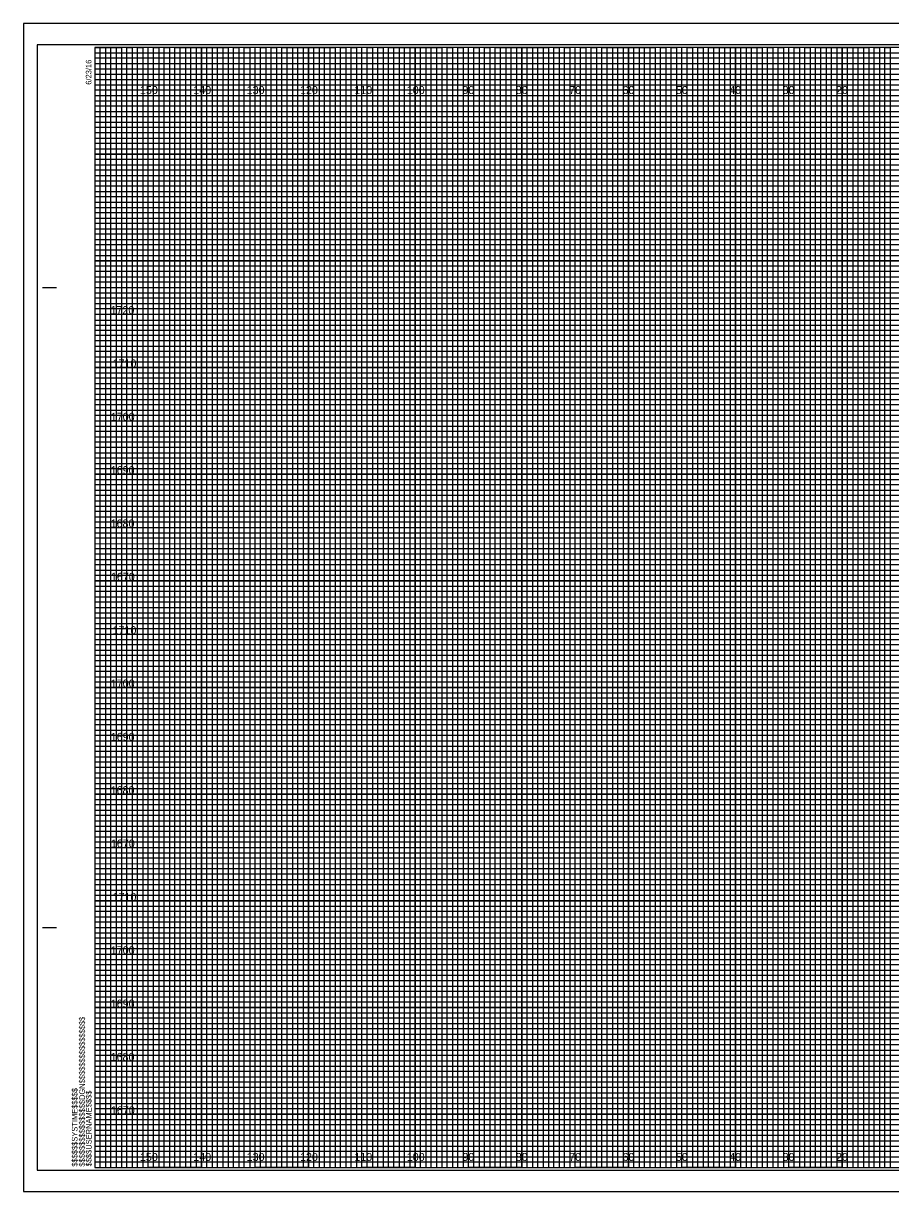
# Model space of a CAD drawing. Extents: x -13 to 323, y -5 to 434.
# Drawn here: x -13.4 to 149.1, y 215.5 to 434.5 of the extents above; entities that cross this region are included whole.
import ezdxf

# ---------------------------------------------------------------- set-up
doc = ezdxf.new("R2010")
doc.units = 0
for name, color, linetype in [('Prop Horizontal Alignment', 7, 'Continuous'), ('Raster_Level_0', 7, 'Continuous'), ('Sheet Cross Section CELL', 7, 'Continuous'), ('Sheet Cross Section Grid Major CELL', 7, 'Continuous'), ('Sheet Cross Section Grid Middle CELL', 7, 'Continuous'), ('Sheet Cross Section Grid Minor 1 CELL', 7, 'Continuous'), ('Sheet Cross Section Grid Minor 2 CELL', 7, 'Continuous'), ('Sheet Cutting Line CELL', 7, 'Continuous'), ('Sheet DOT Grid CELL', 7, 'Continuous'), ('Sheet Plot Border Inside CELL', 7, 'Continuous'), ('Sheet Plot Border Outside CELL', 7, 'Continuous')]:
    doc.layers.add(name, color=color, linetype=linetype)

msp = doc.modelspace()

# ---------------------------------------------------------------- linework, layer by layer
at = {"layer": 'Sheet Cross Section CELL'}
for p, q in [((-9.8, 385), (-7.3, 385)), ((-9.7, 385), (-7.2, 385)), ((-9.8, 265), (-7.3, 265)), ((-9.7, 265), (-7.2, 265)), ((0, 220), (0, 220)), ((0, 220), (0, 220)), ((0, 220), (0, 220)), ((0, 220), (0, 220)), ((0, 220), (0, 220)), ((0, 220), (0, 220)), ((0, 220), (0, 220))]:
    msp.add_line(p, q, dxfattribs=at)
msp.add_lwpolyline([(320, 430), (0, 430), (0, 220), (320, 220)], close=True, dxfattribs=at)
at = {"layer": 'Sheet Cross Section Grid Major CELL'}
for p, q in [((10, 430), (0, 430)), ((10, 220), (10, 430)), ((30, 430), (20, 430)), ((20, 430), (20, 220)), ((30, 220), (30, 430)), ((50, 430), (40, 430)), ((40, 430), (40, 220)), ((50, 220), (50, 430)), ((70, 430), (60, 430)), ((60, 430), (60, 220)), ((70, 220), (70, 430)), ((90, 430), (80, 430)), ((80, 430), (80, 220)), ((90, 220), (90, 430)), ((110, 430), (100, 430)), ((100, 430), (100, 220)), ((110, 220), (110, 430)), ((130, 430), (120, 430)), ((120, 430), (120, 220)), ((130, 220), (130, 430)), ((150, 430), (140, 430)), ((140, 430), (140, 220)), ((20, 220), (10, 220)), ((40, 220), (30, 220)), ((60, 220), (50, 220)), ((80, 220), (70, 220)), ((100, 220), (90, 220)), ((120, 220), (110, 220)), ((140, 220), (130, 220))]:
    msp.add_line(p, q, dxfattribs=at)
for points in [[(0, 420), (320, 420), (320, 410), (0, 410)], [(0, 400), (320, 400), (320, 390), (0, 390)], [(0, 380), (320, 380), (320, 370), (0, 370)], [(0, 360), (320, 360), (320, 350), (0, 350)], [(0, 340), (320, 340), (320, 330), (0, 330)], [(0, 320), (320, 320), (320, 310), (0, 310)], [(0, 300), (320, 300), (320, 290), (0, 290)], [(0, 280), (320, 280), (320, 270), (0, 270)], [(0, 260), (320, 260), (320, 250), (0, 250)], [(0, 240), (320, 240), (320, 230), (0, 230)]]:
    msp.add_lwpolyline(points, dxfattribs=at)
at = {"layer": 'Sheet Cross Section Grid Middle CELL'}
for points in [[(0, 430), (5, 430), (5, 220), (15, 220), (15, 430), (25, 430), (25, 220), (35, 220), (35, 430), (45, 430), (45, 220), (55, 220), (55, 430), (65, 430), (65, 220), (75, 220), (75, 430), (85, 430), (85, 220), (95, 220), (95, 430), (105, 430), (105, 220), (115, 220), (115, 430), (125, 430), (125, 220), (135, 220), (135, 430), (145, 430), (145, 220), (155, 220)], [(0, 425), (275, 425)], [(0, 405), (320, 405), (320, 415), (0, 415)], [(0, 385), (320, 385), (320, 395), (0, 395)], [(0, 365), (320, 365), (320, 375), (0, 375)], [(0, 345), (320, 345), (320, 355), (0, 355)], [(0, 325), (320, 325), (320, 335), (0, 335)], [(0, 305), (320, 305), (320, 315), (0, 315)], [(0, 285), (320, 285), (320, 295), (0, 295)], [(0, 265), (320, 265), (320, 275), (0, 275)], [(0, 245), (320, 245), (320, 255), (0, 255)], [(0, 225), (320, 225), (320, 235), (0, 235)]]:
    msp.add_lwpolyline(points, dxfattribs=at)
at = {"layer": 'Sheet Cross Section Grid Minor 1 CELL'}
for p, q in [((0, 429), (260, 429)), ((260, 427.98), (0, 427.98)), ((0, 427.98), (0, 427)), ((0, 427), (260, 427)), ((260, 425.89), (0, 425.89)), ((0, 425.89), (0, 424)), ((0, 424), (320, 424))]:
    msp.add_line(p, q, dxfattribs=at)
for points in [[(0, 423), (270, 423), (320, 423), (320, 422), (0, 422)], [(0, 421), (320, 421), (320, 419), (0, 419)], [(0, 418), (320, 418), (320, 417), (0, 416.98)], [(0, 416), (320, 416), (320, 414), (0, 414)], [(0, 413), (320, 413), (320, 412), (0, 412)], [(0, 411), (320, 411), (320, 409), (0, 409)], [(0, 408), (320, 408), (320, 407), (0, 407)], [(0, 406), (320, 406), (320, 404), (0, 404)], [(0, 403), (320, 403), (320, 402), (0, 402)], [(0, 401), (320, 401), (320, 399), (0, 399)], [(0, 398), (320, 398), (320, 397), (0, 397)], [(0, 396), (320, 396), (320, 393.95), (320, 393), (320, 392), (0, 392)], [(0, 394), (320, 394), (320, 393), (0, 393)], [(0, 391), (320, 391), (320, 389), (0, 389.03)], [(0, 389.03), (320, 389), (320, 388), (0, 388)], [(0, 387), (320, 387), (320, 386), (0, 386)], [(0, 384), (320, 384), (320, 383), (0, 383)], [(0, 382), (320, 382), (320, 381), (0, 381)], [(-0.07, 378.89), (320, 378.89), (320, 377.88), (-0.07, 377.88)], [(0, 377), (320, 377), (320, 376), (0, 376)], [(0, 374), (320, 374), (320, 373), (0, 373)], [(0, 372), (320, 372), (320, 371), (0, 371)], [(0, 369), (320, 369), (320, 368), (0, 368)], [(0, 367), (320, 367), (320, 366), (0, 366)], [(0, 364), (320, 364), (320, 363), (0, 363)], [(0, 362), (320, 362), (320, 361), (0, 361)], [(0, 359), (320, 359), (319.99, 357.98), (0, 358)], [(0, 357), (320, 357), (320, 356), (0, 356)], [(0, 354), (320, 354), (320, 353), (0, 353)], [(0, 352), (320, 352), (320, 351), (0, 351)], [(0, 349), (320, 349), (320, 348), (0, 348)], [(0, 347), (320, 347), (320, 346), (0, 346)], [(0, 344), (320, 344), (320, 343), (0, 343)], [(0, 342), (320, 342), (320, 341), (0, 341)], [(0, 339), (320, 339), (320, 338), (0, 338)], [(0, 336.99), (320.07, 336.91), (320, 336), (0, 336)], [(0, 334), (320, 334), (320, 333), (0, 333)], [(0, 332), (320, 332), (320, 331), (0, 331)], [(0, 329), (320, 329), (320, 328), (0, 328)], [(0, 327), (320, 327), (320, 326), (0, 326)], [(0, 324), (320, 324), (320, 323), (0, 323)], [(0, 322), (320, 322), (320, 321), (0, 321)], [(0, 319), (320, 319), (320, 318), (0, 318)], [(0, 317), (320, 317), (320, 316), (0, 316)], [(0, 314), (320, 314), (320, 313), (0, 313)], [(0, 312), (320, 312), (320, 311), (0, 311)], [(0, 309), (320, 309), (320, 308), (0, 308)], [(0, 307), (320, 307), (320, 306), (0, 306)], [(0, 304), (320, 304), (320, 303), (0, 303)], [(0, 302), (320, 302), (320, 301), (0, 301)], [(0, 299), (320, 299), (319.99, 297.98), (0, 298)], [(0, 297), (320, 297), (320, 296), (0, 296)], [(0, 294), (320, 294), (320, 293), (0, 293)], [(0, 292), (320, 292), (320, 291), (0, 291)], [(0, 289), (320, 289), (320, 288), (0, 288)], [(0, 287), (320, 287), (320, 286), (0, 286)], [(0, 284), (320, 284), (320, 283), (0, 283)], [(0, 282), (320, 282), (320, 281), (0, 281)], [(0, 279), (320, 279), (320, 278), (0, 278)], [(0, 276.99), (320.07, 276.91), (320, 276), (0, 276)], [(0, 274), (320, 274), (320, 273), (0, 273)], [(0, 272), (320, 272), (320, 271), (0, 271)], [(0, 269), (320, 269), (320, 268), (0, 268)], [(0, 267), (320, 267), (320, 266), (0, 266)], [(0, 264), (320, 264), (320, 263), (0, 263)], [(0, 262), (320, 262), (320, 261), (0, 261)], [(0, 259), (320, 259), (320, 258), (0, 258)], [(0, 257), (320, 257), (320, 256), (0, 256)], [(0, 254), (320, 254), (320, 253), (0, 253)], [(0, 252), (320, 252), (320, 251), (0, 251)], [(0, 249), (320, 249), (320, 248), (0, 248)], [(0, 247), (320, 247), (320, 246), (0, 246)], [(0, 244), (320, 244), (320, 243), (0, 243)], [(0, 242), (320, 242), (320, 241), (0, 241)], [(0, 239), (320, 239), (320, 238), (0, 238)], [(0, 237), (320, 237), (320, 236), (0, 236)], [(0, 234), (320, 234), (320, 233), (0, 233)], [(0, 232), (320, 232), (320, 231), (0, 231)], [(0, 229), (320, 229), (320, 228), (0, 228)], [(0, 227), (320, 227), (320, 226), (0, 226)], [(0, 224), (320, 224), (320, 223), (0, 223)], [(0, 222), (320, 222), (320, 221), (0, 221)]]:
    msp.add_lwpolyline(points, dxfattribs=at)
at = {"layer": 'Sheet Cross Section Grid Minor 2 CELL'}
for points in [[(0, 220), (1, 220), (1, 430), (2, 430), (2, 220)], [(2, 220), (3, 220), (3, 430), (4, 430), (4, 220)], [(5, 220), (6, 220), (6, 430), (7, 430), (7, 220)], [(7, 220), (8, 220), (8, 430), (9, 430), (9, 220)], [(10, 220), (11, 220), (11, 430), (12, 430), (12, 220)], [(12, 220), (13, 220), (13, 430), (14, 430), (14, 220)], [(15, 220), (16, 220), (16, 430), (17, 430), (17, 220)], [(17, 220), (18, 220), (18, 430), (19, 430), (19, 220)], [(20, 220), (21, 220), (21, 430), (22, 430), (22, 220)], [(22, 220), (23, 220), (23, 430), (24, 430), (24, 220)], [(25, 220), (26, 220), (26, 430), (27, 430), (27, 220)], [(27, 220), (28, 220), (28, 430), (29, 430), (29, 220)], [(30, 220), (31, 220), (31, 430), (32, 430), (32, 220)], [(32, 220), (33, 220), (33, 430), (34, 430), (34, 220)], [(35, 220), (36, 220), (36, 430), (37, 430), (37, 220)], [(37, 220), (38, 220), (38, 430), (39, 430), (39, 220)], [(40, 220), (41, 220), (41, 430), (42, 430), (42, 220)], [(42, 220), (43, 220), (43, 430), (44, 430), (44, 220)], [(45, 220), (46, 220), (46, 430), (47, 430), (47, 220)], [(47, 220), (48, 220), (48, 430), (49, 430), (49, 220)], [(50, 220), (51, 220), (51, 430), (52, 430), (52, 220)], [(52, 220), (53, 220), (53, 430), (54, 430), (54, 220)], [(55, 220), (56, 220), (56, 430), (57, 430), (57, 220)], [(57, 220), (58, 220), (58, 430), (59, 430), (59, 220)], [(60, 220), (61, 220), (61, 430), (62, 430), (62, 220)], [(62, 220), (63, 220), (63, 430), (64, 430), (64, 220)], [(65, 220), (66, 220), (66, 430), (67, 430), (67, 220)], [(67, 220), (68, 220), (68, 430), (69, 430), (69, 220)], [(70, 220), (71, 220), (71, 430), (72, 430), (72, 220)], [(72, 220), (73, 220), (73, 430), (74, 430), (74, 220)], [(75, 220), (76, 220), (76, 430), (77, 430), (77, 220)], [(77, 220), (78, 220), (78, 430), (79, 430), (79, 220)], [(80, 220), (81, 220), (81, 430), (82, 430), (82, 220)], [(82, 220), (83, 220), (83, 430), (84, 430), (84, 220)], [(85, 220), (86, 220), (86, 430), (87, 430), (87, 220)], [(87, 220), (88, 220), (88, 430), (89, 430), (89, 220)], [(90, 220), (91, 220), (91, 430), (92, 430), (92, 220)], [(92, 220), (93, 220), (93, 430), (94, 430), (94, 220)], [(95, 220), (96, 220), (96, 430), (97, 430), (97, 220)], [(97, 220), (98, 220), (98, 430), (99, 430), (99, 220)], [(100, 220), (101, 220), (101, 430), (102, 430), (102, 220)], [(102, 220), (103, 220), (103, 430), (104, 430), (104, 220)], [(105, 220), (106, 220), (106, 430), (107, 430), (107, 220)], [(107, 220), (108, 220), (108, 430), (109, 430), (109, 220)], [(110, 220), (111, 220), (111, 430), (112, 430), (112, 220)], [(112, 220), (113, 220), (113, 430), (114, 430), (114, 220)], [(115, 220), (116, 220), (116, 430), (117, 430), (117, 220)], [(117, 220), (118, 220), (118, 430), (119, 430), (119, 220)], [(120, 220), (121, 220), (121, 430), (122, 430), (122, 220)], [(122, 220), (123, 220), (123, 430), (124, 430), (124, 220)], [(125, 220), (126, 220), (126, 430), (127, 430), (127, 220)], [(127, 220), (128, 220), (128, 430), (129, 430), (129, 220)], [(130, 220), (131, 220), (131, 430), (132, 430), (132, 220)], [(132, 220), (133, 220), (133, 430), (134, 430), (134, 220)], [(135, 220), (136, 220), (136, 430), (137, 430), (137, 220)], [(137, 220), (138, 220), (138, 430), (139, 430), (139, 220)], [(140, 220), (141, 220), (141, 430), (142, 430), (142, 220)], [(142, 220), (143, 220), (143, 430), (144, 430), (144, 220)], [(145, 220), (146, 220), (146, 430), (147, 430), (147, 220)], [(147, 220), (148, 220), (148, 430), (149, 430), (149, 220)]]:
    msp.add_lwpolyline(points, dxfattribs=at)
at = {"layer": 'Sheet Cutting Line CELL'}
for p, q in [((323.3, 434.5), (-13.4, 434.5)), ((-13.4, 434.5), (-13.4, 215.5)), ((-13.4, 215.5), (323.3, 215.5))]:
    msp.add_line(p, q, dxfattribs=at)
at = {"layer": 'Sheet DOT Grid CELL'}
for p, q in [((10, 220), (10, 430)), ((20, 220), (20, 430)), ((30, 220), (30, 430)), ((40, 220), (40, 430)), ((50, 220), (50, 430)), ((60, 220), (60, 430)), ((70, 220), (70, 430)), ((80, 220), (80, 430)), ((90, 220), (90, 430)), ((100, 220), (100, 430)), ((110, 220), (110, 430)), ((120, 220), (120, 430)), ((130, 220), (130, 430)), ((140, 220), (140, 430)), ((0, 420), (320, 420)), ((0, 410), (320, 410)), ((0, 400), (320, 400)), ((0, 390), (320, 390)), ((0, 380), (320, 380)), ((0, 370), (320, 370)), ((0, 360), (320, 360)), ((0, 350), (320, 350)), ((0, 340), (320, 340)), ((0, 330), (320, 330)), ((0, 320), (320, 320)), ((0, 310), (320, 310)), ((0, 300), (320, 300)), ((0, 290), (320, 290)), ((0, 280), (320, 280)), ((0, 270), (320, 270)), ((0, 260), (320, 260)), ((0, 250), (320, 250)), ((0, 240), (320, 240)), ((0, 230), (320, 230))]:
    msp.add_line(p, q, dxfattribs=at)
at = {"layer": 'Sheet Plot Border Inside CELL'}
msp.add_lwpolyline([(-10.8, 219.5), (322.4, 219.5), (322.4, 430.5), (-10.8, 430.5)], close=True, dxfattribs=at)
at = {"layer": 'Sheet Plot Border Outside CELL'}
msp.add_lwpolyline([(-13.4, 215.5), (323.3, 215.5), (323.3, 434.5), (-13.4, 434.5)], close=True, dxfattribs=at)

# ---------------------------------------------------------------- texts
at = {"layer": 'Prop Horizontal Alignment'}
for s, p in [('1720', (2.93, 380)), ('1710', (3.31, 370)), ('1700', (2.98, 360)), ('1690', (2.97, 350)), ('1680', (2.95, 340)), ('1670', (3, 330)), ('1710', (3.31, 320)), ('1700', (2.98, 310)), ('1690', (2.97, 300)), ('1680', (2.95, 290)), ('1670', (3, 280)), ('1710', (3.31, 270)), ('1700', (2.98, 260)), ('1690', (2.97, 250)), ('1680', (2.95, 240)), ('1670', (3, 230))]:
    msp.add_text(s, height=1.5, dxfattribs=at).set_placement(p)
at = {"layer": 'Raster_Level_0'}
for s, p in [('150', (8.44, 421.25)), ('140', (18.44, 421.25)), ('130', (28.44, 421.25)), ('120', (38.44, 421.25)), ('110', (48.62, 421.25)), ('100', (58.44, 421.25)), ('90', (68.86, 421.25)), ('80', (78.86, 421.25)), ('70', (88.86, 421.25)), ('60', (98.86, 421.25)), ('50', (108.86, 421.25)), ('40', (118.86, 421.25)), ('30', (128.86, 421.25)), ('20', (138.86, 421.25)), ('150', (8.44, 221.25)), ('140', (18.44, 221.25)), ('130', (28.44, 221.25)), ('120', (38.44, 221.25)), ('110', (48.62, 221.25)), ('100', (58.44, 221.25)), ('90', (68.86, 221.25)), ('80', (78.86, 221.25)), ('70', (88.86, 221.25)), ('60', (98.86, 221.25)), ('50', (108.86, 221.25)), ('40', (118.86, 221.25)), ('30', (128.86, 221.25)), ('20', (138.86, 221.25))]:
    msp.add_text(s, height=1.5, dxfattribs=at).set_placement(p)
at = {"layer": 'Sheet Cross Section CELL'}
for s, p in [('6/23/16', (-0.65, 423)), ('$$$$$$$$$$$$$$$$DGN$$$$$$$$$$$$$$$$', (-1.88, 220.18)), ('$$$$$$SYSTIME$$$$$', (-3.26, 220.18)), ('$$$$USERNAME$$$$', (-0.62, 220.23))]:
    msp.add_text(s, height=1.05, rotation=90, dxfattribs=at).set_placement(p)

doc.saveas('drawing.dxf')
